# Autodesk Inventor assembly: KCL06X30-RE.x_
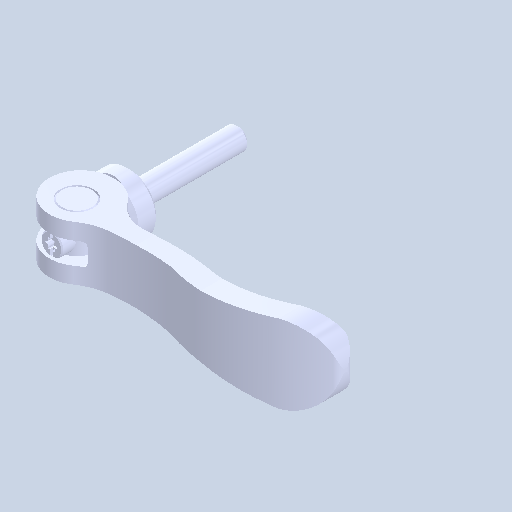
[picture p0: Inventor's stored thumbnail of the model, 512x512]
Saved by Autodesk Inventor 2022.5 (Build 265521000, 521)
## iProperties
Created: 2024-08
Part Number: KCL06X30-RE.x_
Document SubType Name: Assembly
Designer: ImaoCorp
Author: ImaoCorp
Sending System: SOLIDWORKS 2022-2022290
MC: AMD64
MC_MODEL: Intel64 Family 6 Model 60 Stepping 3, GenuineIntel
OS: Windows_NT
FRU: Parasolid Version 33.1, build 260,  4-25-2022
FORMAT: text
GUISE: transmit
KEY: FILEKCL06X30-RE.x_t
DATE: Thu Aug 29 10:49:47 2024
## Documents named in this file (5)
- Y:\5.更新分\2024年対応\1001_KCL\データ\kcl06x30-re\KCL06X30-RE.x_.iam
- Y:\5.更新分\2024年対応\1001_KCL\データ\kcl06x30-re\KCL06X30-RE_01.ipt
- Y:\5.更新分\2024年対応\1001_KCL\データ\kcl06x30-re\KCL06X30-RE_02.ipt
- Y:\5.更新分\2024年対応\1001_KCL\データ\kcl06x30-re\KCL06X30-RE_03.ipt
- Y:\5.更新分\2024年対応\1001_KCL\データ\kcl06x30-re\KCL06X30-RE_04.ipt
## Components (4 placed, 4 different names)
1. KCL06X30-RE_01
2. KCL06X30-RE_02
3. KCL06X30-RE_03
4. KCL06X30-RE_04
